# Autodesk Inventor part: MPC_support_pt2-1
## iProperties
Shininess: 64.0
Length Units: 11269
Angle Units: 11279
Time Units: 11290
Mass Units: 11283
Length Display Precision: 3
Angle Display Precision: 2
Compacted: True
Part Number: MPC_support_pt2-1
Document SubType Name: Modeling
Created: 2004-08
Designer: John Blackburn
Manufacturer: Standard
Standards Organization: Custom
Material: Aluminum-6061
Density: 0.0
Volumn: 0.0
Area: 0.0
PropertySet Name: Model Information
Control State: 0
Master: False
Checked Out: False
Author: John Blackburn
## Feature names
1. Extrusion1
2. Hole1
3. Hole2
